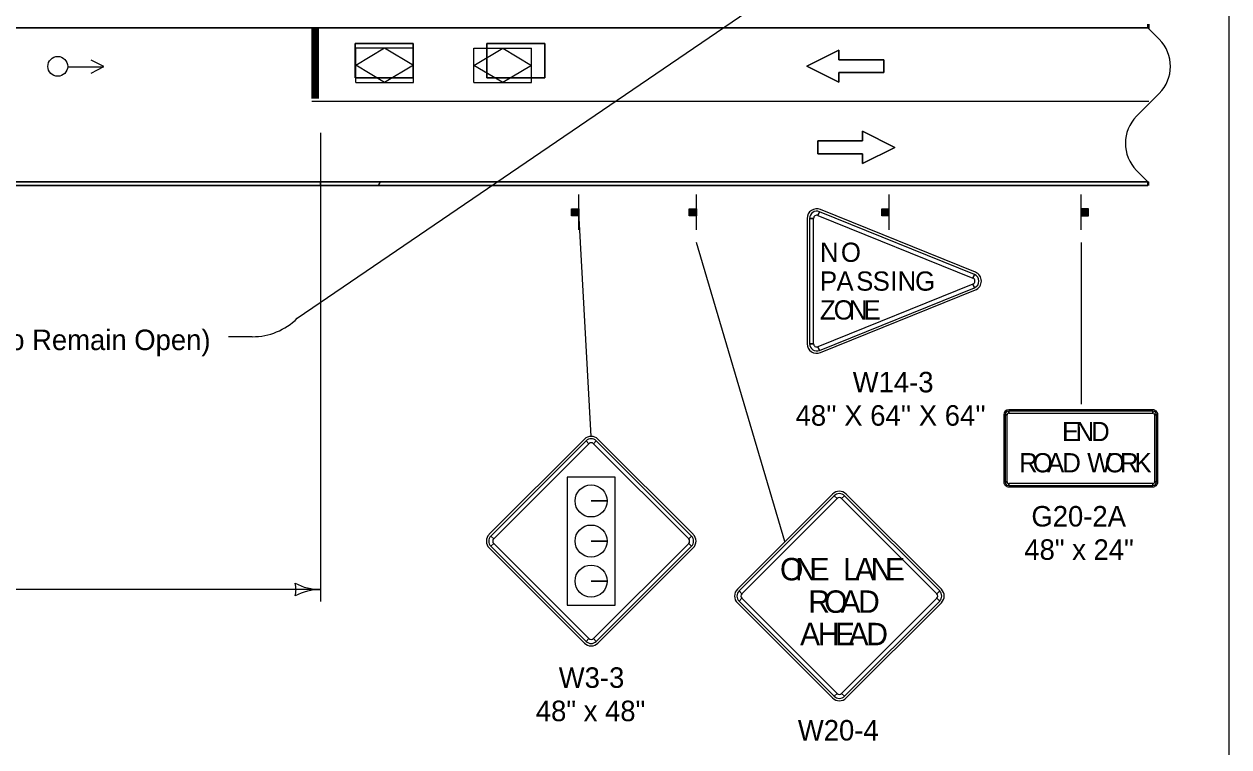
# Model space of a CAD drawing. Extents: x -2134934 to -2122394, y -2140205 to -2137036.
# Drawn here: x -2128036 to -2127097, y -2138106 to -2137542 of the extents above; entities that cross this region are included whole.
import ezdxf

# ---------------------------------------------------------------- set-up
doc = ezdxf.new("R2010")
doc.units = 0
for name, color, linetype in [('Barrier', 7, 'Continuous'), ('BridgeSuperStructureExisting', 7, 'Continuous'), ('Default', 7, 'Continuous'), ('DsnShtPlotIdentification', 7, 'Continuous'), ('DsnShtPlotShape', 7, 'Continuous'), ('dsnTextFinalPlan', 7, 'Continuous')]:
    doc.layers.add(name, color=color, linetype=linetype)

msp = doc.modelspace()

# ---------------------------------------------------------------- linework, layer by layer
at = {"layer": 'Barrier'}
for p, q in [((-2127417.35, -2137691.45), (-2127416.18, -2137688.56)), ((-2127294.65, -2137735.69), (-2127415.48, -2137686.82)), ((-2127425.79, -2137693.77), (-2127425.79, -2137791.52)), ((-2127423.92, -2137693.77), (-2127420.79, -2137693.77)), ((-2127295.36, -2137737.43), (-2127296.53, -2137740.33)), ((-2127296.53, -2137744.96), (-2127295.36, -2137747.86)), ((-2127415.48, -2137798.48), (-2127294.65, -2137749.6)), ((-2127420.79, -2137791.52), (-2127423.92, -2137791.52)), ((-2127416.18, -2137796.74), (-2127417.35, -2137793.84)), ((-2127272.42, -2137846.89), (-2127272.42, -2137899.39)), ((-2127271.48, -2137846.89), (-2127269.92, -2137846.89)), ((-2127156.17, -2137843.14), (-2127268.67, -2137843.14)), ((-2127268.67, -2137845.64), (-2127268.67, -2137844.08)), ((-2127156.17, -2137844.08), (-2127156.17, -2137845.64)), ((-2127154.92, -2137846.89), (-2127153.35, -2137846.89)), ((-2127152.42, -2137899.39), (-2127152.42, -2137846.89)), ((-2127599.5, -2137865.99), (-2127673.75, -2137940.23)), ((-2127598.17, -2137867.31), (-2127595.96, -2137869.52)), ((-2127592.43, -2137869.52), (-2127590.22, -2137867.31)), ((-2127514.65, -2137940.23), (-2127588.89, -2137865.99)), ((-2127269.92, -2137899.39), (-2127271.48, -2137899.39)), ((-2127268.67, -2137902.2), (-2127268.67, -2137900.64)), ((-2127268.67, -2137903.14), (-2127156.17, -2137903.14)), ((-2127156.17, -2137900.64), (-2127156.17, -2137902.2)), ((-2127153.35, -2137899.39), (-2127154.92, -2137899.39)), ((-2127581.79, -2137914.21), (-2127594.29, -2137914.21)), ((-2127594.29, -2137914.21), (-2127581.79, -2137914.21)), ((-2127405.98, -2137908.8), (-2127480.23, -2137983.04)), ((-2127404.66, -2137910.12), (-2127402.45, -2137912.33)), ((-2127398.91, -2137912.33), (-2127396.7, -2137910.12)), ((-2127321.13, -2137983.04), (-2127395.38, -2137908.8)), ((-2127670.21, -2137943.77), (-2127672.42, -2137941.56)), ((-2127515.97, -2137941.56), (-2127518.18, -2137943.77)), ((-2127673.75, -2137950.84), (-2127599.5, -2138025.09)), ((-2127672.42, -2137949.51), (-2127670.21, -2137947.3)), ((-2127581.79, -2137945.46), (-2127594.29, -2137945.46)), ((-2127594.29, -2137945.46), (-2127581.79, -2137945.46)), ((-2127588.89, -2138025.09), (-2127514.65, -2137950.84)), ((-2127518.18, -2137947.3), (-2127515.97, -2137949.51)), ((-2127581.79, -2137976.71), (-2127594.29, -2137976.71)), ((-2127594.29, -2137976.71), (-2127581.79, -2137976.71)), ((-2127476.7, -2137986.58), (-2127478.9, -2137984.37)), ((-2127322.46, -2137984.37), (-2127324.67, -2137986.58)), ((-2127480.23, -2137993.65), (-2127405.98, -2138067.9)), ((-2127478.9, -2137992.32), (-2127476.7, -2137990.11)), ((-2127395.38, -2138067.9), (-2127321.13, -2137993.65)), ((-2127324.67, -2137990.11), (-2127322.46, -2137992.32)), ((-2127595.96, -2138021.55), (-2127598.17, -2138023.76)), ((-2127590.22, -2138023.76), (-2127592.43, -2138021.55)), ((-2127402.45, -2138064.36), (-2127404.66, -2138066.57)), ((-2127396.7, -2138066.57), (-2127398.91, -2138064.36))]:
    msp.add_line(p, q, dxfattribs=at)
for points in [[(-2127295.36, -2137737.43), (-2127416.18, -2137688.56), (-2127417.35, -2137691.45), (-2127296.53, -2137740.33), (-2127295.36, -2137737.43)], [(-2127423.92, -2137693.77), (-2127423.92, -2137791.52), (-2127420.79, -2137791.52), (-2127420.79, -2137693.77), (-2127423.92, -2137693.77)], [(-2127416.18, -2137796.74), (-2127295.36, -2137747.86), (-2127296.53, -2137744.96), (-2127417.35, -2137793.84), (-2127416.18, -2137796.74)], [(-2127271.48, -2137846.89), (-2127271.48, -2137899.39), (-2127269.92, -2137899.39), (-2127269.92, -2137846.89), (-2127271.48, -2137846.89)], [(-2127156.17, -2137844.08), (-2127268.67, -2137844.08), (-2127268.67, -2137845.64), (-2127156.17, -2137845.64), (-2127156.17, -2137844.08)], [(-2127153.35, -2137899.39), (-2127153.35, -2137846.89), (-2127154.92, -2137846.89), (-2127154.92, -2137899.39), (-2127153.35, -2137899.39)], [(-2127598.17, -2137867.31), (-2127672.42, -2137941.56), (-2127670.21, -2137943.77), (-2127595.96, -2137869.52), (-2127598.17, -2137867.31)], [(-2127515.97, -2137941.56), (-2127590.22, -2137867.31), (-2127592.43, -2137869.52), (-2127518.18, -2137943.77), (-2127515.97, -2137941.56)], [(-2127575.46, -2137895.59), (-2127612.93, -2137895.59), (-2127612.93, -2137995.48), (-2127575.46, -2137995.48), (-2127575.46, -2137895.59)], [(-2127268.67, -2137902.2), (-2127156.17, -2137902.2), (-2127156.17, -2137900.64), (-2127268.67, -2137900.64), (-2127268.67, -2137902.2)], [(-2127404.66, -2137910.12), (-2127478.9, -2137984.37), (-2127476.7, -2137986.58), (-2127402.45, -2137912.33), (-2127404.66, -2137910.12)], [(-2127322.46, -2137984.37), (-2127396.7, -2137910.12), (-2127398.91, -2137912.33), (-2127324.67, -2137986.58), (-2127322.46, -2137984.37)], [(-2127672.42, -2137949.51), (-2127598.17, -2138023.76), (-2127595.96, -2138021.55), (-2127670.21, -2137947.3), (-2127672.42, -2137949.51)], [(-2127590.22, -2138023.76), (-2127515.97, -2137949.51), (-2127518.18, -2137947.3), (-2127592.43, -2138021.55), (-2127590.22, -2138023.76)], [(-2127478.9, -2137992.32), (-2127404.66, -2138066.57), (-2127402.45, -2138064.36), (-2127476.7, -2137990.11), (-2127478.9, -2137992.32)], [(-2127396.7, -2138066.57), (-2127322.46, -2137992.32), (-2127324.67, -2137990.11), (-2127398.91, -2138064.36), (-2127396.7, -2138066.57)]]:
    msp.add_lwpolyline(points, close=True, dxfattribs=at)
for centre in [(-2127594.29, -2137914.21), (-2127594.29, -2137945.46), (-2127594.29, -2137976.71)]:
    msp.add_circle(centre, 12.5, dxfattribs=at)
for centre, radius, start, end in [((-2127418.29, -2137693.77), 7.5, 67.97571, 179.99985), ((-2127418.29, -2137693.77), 5.62, 67.97571, 179.99985), ((-2127418.29, -2137693.77), 2.5, 67.97571, 179.99985), ((-2127297.47, -2137742.65), 7.5, 292.02456, 67.97598), ((-2127297.47, -2137742.65), 2.5, 292.02456, 67.97541), ((-2127297.47, -2137742.65), 5.62, 292.02456, 67.97541), ((-2127418.29, -2137791.52), 7.5, 179.99985, 292.02456), ((-2127418.29, -2137791.52), 5.62, 179.99985, 292.02456), ((-2127418.29, -2137791.52), 2.5, 179.99985, 292.02456), ((-2127268.67, -2137846.89), 3.75, 90.00021, 179.99985), ((-2127268.67, -2137846.89), 2.81, 90.00021, 179.99985), ((-2127268.67, -2137846.89), 1.25, 90.00021, 179.99985), ((-2127156.17, -2137846.89), 3.75, 0, 90.00021), ((-2127156.17, -2137846.89), 2.81, 0, 90.00021), ((-2127156.17, -2137846.89), 1.25, 0, 90.00021), ((-2127594.2, -2137871.29), 7.5, 44.99999, 134.99974), ((-2127594.2, -2137871.29), 5.62, 44.99999, 134.99974), ((-2127594.2, -2137871.29), 2.5, 44.99999, 134.99974), ((-2127268.67, -2137899.39), 3.75, 179.99985, 270.00006), ((-2127268.67, -2137899.39), 2.81, 179.99985, 270.00006), ((-2127268.67, -2137899.39), 1.25, 179.99985, 270.00006), ((-2127156.17, -2137899.39), 3.75, 270.00006, 0.00027), ((-2127156.17, -2137899.39), 2.81, 270.00006, 0.00027), ((-2127156.17, -2137899.39), 1.25, 270.00006, 0.00027), ((-2127400.68, -2137914.1), 7.5, 44.99999, 134.99974), ((-2127400.68, -2137914.1), 5.62, 44.99999, 134.99974), ((-2127400.68, -2137914.1), 2.5, 44.99999, 134.99974), ((-2127668.44, -2137945.54), 7.5, 134.99974, 224.99995), ((-2127668.44, -2137945.54), 5.62, 134.99974, 224.99995), ((-2127519.95, -2137945.54), 5.62, 315.00016, 44.9998), ((-2127519.95, -2137945.54), 7.5, 315.00016, 44.9998), ((-2127668.44, -2137945.54), 2.5, 134.99974, 224.99995), ((-2127519.95, -2137945.54), 2.5, 315.00016, 44.9998), ((-2127474.93, -2137988.35), 7.5, 134.99974, 224.99995), ((-2127474.93, -2137988.35), 5.62, 134.99974, 224.99995), ((-2127474.93, -2137988.35), 2.5, 134.99974, 224.99995), ((-2127326.44, -2137988.35), 2.5, 315.00016, 44.9998), ((-2127326.44, -2137988.35), 5.62, 315.00016, 44.9998), ((-2127326.44, -2137988.35), 7.5, 315.00016, 44.9998), ((-2127594.2, -2138019.78), 7.5, 224.99995, 315.00016), ((-2127594.2, -2138019.78), 5.62, 224.99995, 315.00016), ((-2127594.2, -2138019.78), 2.5, 224.99995, 315.00016), ((-2127400.68, -2138062.59), 2.5, 224.99995, 315.00016), ((-2127400.68, -2138062.59), 7.5, 224.99995, 315.00016), ((-2127400.68, -2138062.59), 5.62, 224.99995, 315.00016)]:
    msp.add_arc(centre, radius, start, end, dxfattribs=at)
at = {"layer": 'BridgeSuperStructureExisting'}
for p, q in [((-2127823.33, -2137771.69), (-2127460.63, -2137524.39)), ((-2127160.12, -2137545.16), (-2128660.12, -2137545.16)), ((-2127811.95, -2137545.16), (-2127811.95, -2137600.16)), ((-2127810.95, -2137545.16), (-2127810.95, -2137600.16)), ((-2127809.95, -2137545.16), (-2127809.95, -2137600.16)), ((-2127808.95, -2137545.16), (-2127808.95, -2137600.16)), ((-2127807.95, -2137545.16), (-2127807.95, -2137600.16)), ((-2127806.95, -2137545.16), (-2127806.95, -2137600.16)), ((-2127160.12, -2137545.16), (-2127151.33, -2137553.95)), ((-2127151.33, -2137553.95), (-2127160.12, -2137545.16)), ((-2127778.12, -2137557.19), (-2127733.12, -2137557.19)), ((-2127778.12, -2137584.19), (-2127778.12, -2137557.19)), ((-2127733.12, -2137557.19), (-2127778.12, -2137557.19)), ((-2127778.12, -2137557.19), (-2127778.12, -2137584.19)), ((-2127733.12, -2137557.19), (-2127733.12, -2137584.19)), ((-2127733.12, -2137584.19), (-2127733.12, -2137557.19)), ((-2127675.45, -2137557.19), (-2127630.45, -2137557.19)), ((-2127675.45, -2137584.19), (-2127675.45, -2137557.19)), ((-2127630.45, -2137557.19), (-2127675.45, -2137557.19)), ((-2127675.45, -2137557.19), (-2127675.45, -2137584.19)), ((-2127630.45, -2137557.19), (-2127630.45, -2137584.19)), ((-2127630.45, -2137584.19), (-2127630.45, -2137557.19)), ((-2127777.79, -2137587.78), (-2127777.79, -2137560.78)), ((-2127777.79, -2137560.78), (-2127732.79, -2137560.78)), ((-2127732.79, -2137587.78), (-2127732.79, -2137560.78)), ((-2127685.6, -2137587.86), (-2127685.6, -2137560.86)), ((-2127685.6, -2137560.86), (-2127640.6, -2137560.86)), ((-2127640.6, -2137587.86), (-2127640.6, -2137560.86)), ((-2128002.38, -2137575.52), (-2127974.44, -2137575.52)), ((-2127733.12, -2137584.19), (-2127778.12, -2137584.19)), ((-2127778.12, -2137584.19), (-2127733.12, -2137584.19)), ((-2127630.45, -2137584.19), (-2127675.45, -2137584.19)), ((-2127675.45, -2137584.19), (-2127630.45, -2137584.19)), ((-2127777.79, -2137587.78), (-2127732.79, -2137587.78)), ((-2127685.6, -2137587.86), (-2127640.6, -2137587.86)), ((-2127168.91, -2137613.95), (-2127151.33, -2137596.37)), ((-2127151.33, -2137596.38), (-2127168.9, -2137613.95)), ((-2127805.12, -2137627.09), (-2127805.12, -2137992.63)), ((-2127160.12, -2137665.16), (-2127168.91, -2137656.37)), ((-2127168.9, -2137656.38), (-2127160.12, -2137665.16)), ((-2128470.12, -2137665.16), (-2127160.12, -2137665.16)), ((-2127603.79, -2137702.66), (-2127603.79, -2137675.16)), ((-2127511.96, -2137702.66), (-2127511.96, -2137675.16)), ((-2127361.96, -2137702.66), (-2127361.96, -2137675.16)), ((-2127212.15, -2137702.66), (-2127212.15, -2137675.16)), ((-2127609.12, -2137691.8), (-2127609.12, -2137686.21)), ((-2127608.8, -2137686.21), (-2127608.8, -2137691.8)), ((-2127608.58, -2137691.8), (-2127608.58, -2137686.21)), ((-2127608.26, -2137686.21), (-2127608.26, -2137691.8)), ((-2127608.03, -2137691.8), (-2127608.05, -2137686.21)), ((-2127607.62, -2137686.21), (-2127607.6, -2137691.8)), ((-2127607.4, -2137691.8), (-2127607.4, -2137686.21)), ((-2127606.96, -2137686.21), (-2127606.96, -2137691.8)), ((-2127606.59, -2137691.8), (-2127606.59, -2137686.21)), ((-2127606.27, -2137686.21), (-2127606.25, -2137691.8)), ((-2127606.05, -2137691.8), (-2127606.05, -2137686.21)), ((-2127605.78, -2137686.21), (-2127605.78, -2137691.8)), ((-2127605.45, -2137691.8), (-2127605.45, -2137686.21)), ((-2127605.24, -2137686.21), (-2127605.24, -2137691.8)), ((-2127605.01, -2137691.8), (-2127605.01, -2137686.21)), ((-2127604.75, -2137686.21), (-2127604.75, -2137691.8)), ((-2127604.49, -2137691.8), (-2127604.49, -2137686.21)), ((-2127604.21, -2137686.21), (-2127604.21, -2137691.8)), ((-2127594.2, -2137863.79), (-2127603.79, -2137688.91)), ((-2127517.28, -2137691.8), (-2127517.28, -2137686.21)), ((-2127516.96, -2137686.21), (-2127516.96, -2137691.8)), ((-2127516.74, -2137691.8), (-2127516.74, -2137686.21)), ((-2127516.42, -2137686.21), (-2127516.42, -2137691.8)), ((-2127516.19, -2137691.8), (-2127516.21, -2137686.21)), ((-2127515.78, -2137686.21), (-2127515.76, -2137691.8)), ((-2127515.56, -2137691.8), (-2127515.56, -2137686.21)), ((-2127515.13, -2137686.21), (-2127515.13, -2137691.8)), ((-2127514.75, -2137691.8), (-2127514.75, -2137686.21)), ((-2127514.43, -2137686.21), (-2127514.41, -2137691.8)), ((-2127514.21, -2137691.8), (-2127514.21, -2137686.21)), ((-2127513.94, -2137686.21), (-2127513.94, -2137691.8)), ((-2127513.61, -2137691.8), (-2127513.61, -2137686.21)), ((-2127513.4, -2137686.21), (-2127513.4, -2137691.8)), ((-2127513.18, -2137691.8), (-2127513.18, -2137686.21)), ((-2127512.91, -2137686.21), (-2127512.91, -2137691.8)), ((-2127512.65, -2137691.8), (-2127512.65, -2137686.21)), ((-2127512.37, -2137686.21), (-2127512.37, -2137691.8)), ((-2127367.28, -2137691.8), (-2127367.28, -2137686.21)), ((-2127366.96, -2137686.21), (-2127366.96, -2137691.8)), ((-2127366.74, -2137691.8), (-2127366.74, -2137686.21)), ((-2127366.42, -2137686.21), (-2127366.42, -2137691.8)), ((-2127366.19, -2137691.8), (-2127366.21, -2137686.21)), ((-2127365.78, -2137686.21), (-2127365.76, -2137691.8)), ((-2127365.56, -2137691.8), (-2127365.56, -2137686.21)), ((-2127365.13, -2137686.21), (-2127365.13, -2137691.8)), ((-2127364.75, -2137691.8), (-2127364.75, -2137686.21)), ((-2127364.43, -2137686.21), (-2127364.41, -2137691.8)), ((-2127364.21, -2137691.8), (-2127364.21, -2137686.21)), ((-2127363.94, -2137686.21), (-2127363.94, -2137691.8)), ((-2127363.61, -2137691.8), (-2127363.61, -2137686.21)), ((-2127363.4, -2137686.21), (-2127363.4, -2137691.8)), ((-2127363.18, -2137691.8), (-2127363.18, -2137686.21)), ((-2127362.91, -2137686.21), (-2127362.91, -2137691.8)), ((-2127362.65, -2137691.8), (-2127362.65, -2137686.21)), ((-2127362.37, -2137686.21), (-2127362.37, -2137691.8)), ((-2127211.73, -2137686.21), (-2127211.73, -2137691.8)), ((-2127211.45, -2137691.8), (-2127211.45, -2137686.21)), ((-2127211.19, -2137686.21), (-2127211.19, -2137691.8)), ((-2127210.93, -2137691.8), (-2127210.93, -2137686.21)), ((-2127210.7, -2137686.21), (-2127210.7, -2137691.8)), ((-2127210.5, -2137691.8), (-2127210.5, -2137686.21)), ((-2127210.16, -2137686.21), (-2127210.16, -2137691.8)), ((-2127209.9, -2137691.8), (-2127209.9, -2137686.21)), ((-2127209.67, -2137686.21), (-2127209.69, -2137691.8)), ((-2127209.35, -2137691.8), (-2127209.35, -2137686.21)), ((-2127208.98, -2137686.21), (-2127208.98, -2137691.8)), ((-2127208.55, -2137691.8), (-2127208.55, -2137686.21)), ((-2127208.32, -2137686.21), (-2127208.34, -2137691.8)), ((-2127207.91, -2137691.8), (-2127207.89, -2137686.21)), ((-2127207.68, -2137686.21), (-2127207.68, -2137691.8)), ((-2127207.36, -2137691.8), (-2127207.36, -2137686.21)), ((-2127207.14, -2137686.21), (-2127207.14, -2137691.8)), ((-2127206.82, -2137691.8), (-2127206.82, -2137686.21)), ((-2127443.11, -2137945.92), (-2127511.96, -2137712.66)), ((-2127211.96, -2137838.71), (-2127211.96, -2137712.66)), ((-2127858.41, -2137786.07), (-2127876.87, -2137786.07)), ((-2127805.12, -2137983.33), (-2128464.54, -2137983.33))]:
    msp.add_line(p, q, dxfattribs=at)
for points in [[(-2127366.01, -2137579.99), (-2127366.01, -2137569.99), (-2127401.01, -2137569.99), (-2127401.01, -2137562.49), (-2127426.01, -2137574.99), (-2127401.01, -2137587.49), (-2127401.01, -2137579.99)], [(-2127417.52, -2137633.32), (-2127417.52, -2137643.32), (-2127382.52, -2137643.32), (-2127382.52, -2137650.82), (-2127357.52, -2137638.32), (-2127382.52, -2137625.82), (-2127382.52, -2137633.32)], [(-2127603.89, -2137686.21), (-2127603.89, -2137691.84), (-2127609.51, -2137691.84), (-2127609.51, -2137686.21)], [(-2127512.05, -2137686.21), (-2127512.05, -2137691.84), (-2127517.68, -2137691.84), (-2127517.68, -2137686.21)], [(-2127362.05, -2137686.21), (-2127362.05, -2137691.84), (-2127367.68, -2137691.84), (-2127367.68, -2137686.21)], [(-2127212.05, -2137686.21), (-2127212.05, -2137691.84), (-2127206.43, -2137691.84), (-2127206.43, -2137686.21)]]:
    msp.add_lwpolyline(points, close=True, dxfattribs=at)
for points in [[(-2127401.01, -2137579.99), (-2127401.01, -2137587.49), (-2127426.01, -2137574.99), (-2127401.01, -2137562.49), (-2127401.01, -2137569.99), (-2127366.01, -2137569.99), (-2127366.01, -2137579.99), (-2127401.01, -2137579.99)], [(-2127984.07, -2137580.34), (-2127974.07, -2137575.34), (-2127984.07, -2137570.34)], [(-2127382.52, -2137633.32), (-2127382.52, -2137625.82), (-2127357.52, -2137638.32), (-2127382.52, -2137650.82), (-2127382.52, -2137643.32), (-2127417.52, -2137643.32), (-2127417.52, -2137633.32), (-2127382.52, -2137633.32)]]:
    msp.add_lwpolyline(points, dxfattribs=at)
msp.add_circle((-2128010.12, -2137575.16), 7.74, dxfattribs=at)
for centre, radius, start, end in [((-2127172.55, -2137575.16), 30, 315, 45), ((-2127172.55, -2137575.16), 30, 315, 45), ((-2127147.69, -2137635.16), 30, 135, 225), ((-2127147.69, -2137635.16), 30, 135, 225), ((-2127858.41, -2137736.07), 50, 270, 314.56349)]:
    msp.add_arc(centre, radius, start, end, dxfattribs=at)
at = {"layer": 'Default'}
msp.add_lwpolyline([(-2130231.95, -2137035.95), (-2127096.96, -2137035.95), (-2127096.96, -2139045.94), (-2130231.95, -2139045.94)], close=True, dxfattribs=at)
at = {"layer": 'DsnShtPlotIdentification'}
for p, q in [((-2127160.12, -2137545.16), (-2128660.12, -2137545.16)), ((-2128660.12, -2137545.16), (-2127810.12, -2137545.16)), ((-2127808.12, -2137545.16), (-2127807.12, -2137545.16)), ((-2127807.12, -2137545.16), (-2127806.12, -2137545.16)), ((-2127806.12, -2137545.16), (-2127805.12, -2137545.16)), ((-2127805.12, -2137545.16), (-2127160.12, -2137545.16)), ((-2127160.12, -2137545.16), (-2127160.12, -2137542.16)), ((-2127159.5, -2137542.16), (-2127159.5, -2137545.16)), ((-2127159.45, -2137602.66), (-2127811.95, -2137602.66)), ((-2128660.12, -2137665.16), (-2127159.5, -2137665.16)), ((-2127805.12, -2137665.16), (-2128280.26, -2137665.16)), ((-2128278.09, -2137668.16), (-2127805.12, -2137668.16)), ((-2127805.12, -2137668.16), (-2127805.12, -2137665.16)), ((-2127805.12, -2137665.16), (-2127805.12, -2137668.16)), ((-2127758.7, -2137665.16), (-2127805.12, -2137665.16)), ((-2127805.12, -2137668.16), (-2127759.9, -2137668.16)), ((-2127759.9, -2137668.16), (-2127758.7, -2137665.16)), ((-2127758.7, -2137665.16), (-2127759.9, -2137668.16)), ((-2127759.9, -2137668.16), (-2127160.12, -2137668.16)), ((-2127160.12, -2137665.16), (-2127758.7, -2137665.16)), ((-2127160.12, -2137668.16), (-2127160.12, -2137665.16)), ((-2127159.5, -2137668.16), (-2127159.5, -2137665.16))]:
    msp.add_line(p, q, dxfattribs=at)
for points in [[(-2128471.26, -2137545.16), (-2127158.8, -2137545.16)], [(-2127810.12, -2137545.16), (-2127809.12, -2137545.16), (-2127808.12, -2137545.16)], [(-2127160.12, -2137665.16), (-2128470.12, -2137665.16)], [(-2127160.12, -2137668.16), (-2128470.12, -2137668.16)]]:
    msp.add_lwpolyline(points, dxfattribs=at)
at = {"layer": 'DsnShtPlotShape'}
for centre, radius, start, end in [((-2127840.75, -2137983.33), 16.42, 342.26665, 17.73335), ((-2127805.12, -2137940.83), 42.5, 241.92751, 270), ((-2127805.12, -2138025.83), 42.5, 90, 118.07249)]:
    msp.add_arc(centre, radius, start, end, dxfattribs=at)
at = {"layer": 'dsnTextFinalPlan'}
for points in [[(-2127777.79, -2137574.28), (-2127755.29, -2137560.78), (-2127732.79, -2137574.28), (-2127755.29, -2137587.78)], [(-2127685.6, -2137574.36), (-2127663.1, -2137560.86), (-2127640.6, -2137574.36), (-2127663.1, -2137587.86)]]:
    msp.add_lwpolyline(points, close=True, dxfattribs=at)

# ---------------------------------------------------------------- texts
at = {"layer": 'Barrier'}
for s, height, p in [('N', 15, (-2127415.82, -2137727.65)), ('O', 15, (-2127399.48, -2137727.65)), ('P', 15, (-2127415.82, -2137750.15)), ('A', 15, (-2127402.93, -2137750.15)), ('S', 15, (-2127387.58, -2137750.15)), ('S', 15, (-2127374.69, -2137750.15)), ('I', 15, (-2127361.09, -2137750.15)), ('N', 15, (-2127355.23, -2137750.15)), ('G', 15, (-2127341.64, -2137750.15)), ('Z', 15, (-2127415.82, -2137772.65)), ('O', 15, (-2127405.09, -2137772.65)), ('N', 15, (-2127393.26, -2137772.65)), ('E', 15, (-2127381.89, -2137772.65)), ('W14-3', 16, (-2127390.28, -2137829.48)), ("48'' X 64'' X 64''", 16, (-2127434.77, -2137855.47)), ('E', 15, (-2127227.09, -2137867.51)), ('N', 15, (-2127216.47, -2137867.51)), ('D', 15, (-2127204.39, -2137867.51)), ('R', 15, (-2127260.56, -2137891.89)), ('O', 15, (-2127249.87, -2137891.89)), ('A', 15, (-2127238.72, -2137891.89)), ('D', 15, (-2127226.86, -2137891.89)), ('W', 15, (-2127207.4, -2137891.89)), ('O', 15, (-2127193.67, -2137891.89)), ('R', 15, (-2127181.9, -2137891.89)), ('K', 15, (-2127170.61, -2137891.89)), ('G20-2A', 16, (-2127250.95, -2137934.14)), ('48" x 24"', 16, (-2127256.48, -2137960.14)), ('O', 17.5, (-2127446.97, -2137976.16)), ('N', 17.5, (-2127435.19, -2137976.16)), ('E', 17.5, (-2127423.96, -2137976.16)), ('L', 17.5, (-2127397.71, -2137976.16)), ('A', 17.5, (-2127388.52, -2137976.16)), ('N', 17.5, (-2127376.25, -2137976.16)), ('E', 17.5, (-2127365.02, -2137976.16)), ('R', 17.5, (-2127424.86, -2138001.47)), ('O', 17.5, (-2127412.57, -2138001.47)), ('A', 17.5, (-2127399.73, -2138001.47)), ('D', 17.5, (-2127386.08, -2138001.47)), ('A', 17.5, (-2127431.3, -2138026.78)), ('H', 17.5, (-2127417.43, -2138026.78)), ('E', 17.5, (-2127404.21, -2138026.78)), ('A', 17.5, (-2127393.5, -2138026.78)), ('D', 17.5, (-2127379.64, -2138026.78)), ('W3-3', 16, (-2127619.49, -2138060)), ('48" x 48"', 16, (-2127637.37, -2138086)), ('W20-4', 16, (-2127433.05, -2138101.09))]:
    msp.add_text(s, height=height, dxfattribs=at).set_placement(p)
at = {"layer": 'BridgeSuperStructureExisting'}
msp.add_text('Private Drive (To Remain Open)', height=16, dxfattribs=at).set_placement((-2128196.56, -2137796.51))

doc.saveas('drawing.dxf')
